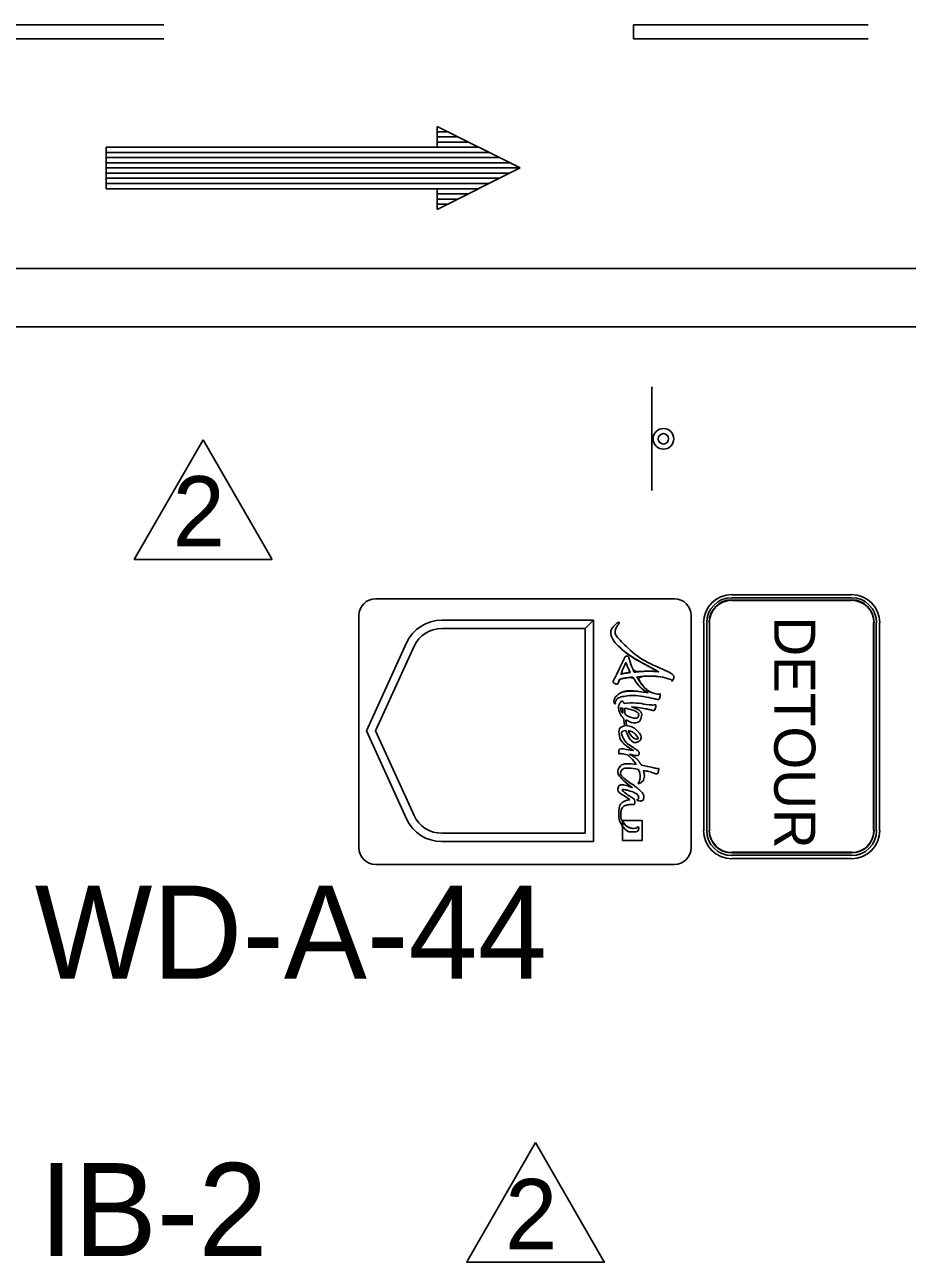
# Model space of a CAD drawing. Extents: x 1806 to 2022, y 110 to 389.
# Drawn here: x 1900.38 to 1918.56, y 195.64 to 221.16 of the extents above; entities that cross this region are included whole.
import ezdxf

# ---------------------------------------------------------------- set-up
doc = ezdxf.new("R2010")
doc.units = 0
for name, color, linetype in [('Level 10', 7, 'Continuous'), ('Level 2', 7, 'Continuous'), ('Level 44', 7, 'Continuous'), ('Level 50', 7, 'Continuous'), ('Level 53', 7, 'Continuous'), ('Level 60', 7, 'Continuous')]:
    doc.layers.add(name, color=color, linetype=linetype)

msp = doc.modelspace()

# ---------------------------------------------------------------- linework, layer by layer
at = {"layer": 'Level 10'}
for p, q in [((1895.86, 216.139), (1957.331, 216.139)), ((1895.86, 214.93), (1957.331, 214.93))]:
    msp.add_line(p, q, dxfattribs=at)
at = {"layer": 'Level 2'}
for p, q in [((1903.243, 221.163), (1898.405, 221.163)), ((1917.757, 221.163), (1912.919, 221.163)), ((1912.919, 221.163), (1912.919, 220.873)), ((1898.405, 220.873), (1903.243, 220.873)), ((1912.919, 220.873), (1917.757, 220.873)), ((1913.762, 209.325), (1907.607, 209.325)), ((1907.26, 208.978), (1907.26, 204.193)), ((1908.969, 208.883), (1912.096, 208.883)), ((1912.096, 208.883), (1911.925, 208.711)), ((1911.925, 208.711), (1912.096, 208.883)), ((1912.096, 208.883), (1912.096, 204.317)), ((1914.109, 208.978), (1914.109, 204.193)), ((1914.109, 208.978), (1914.109, 204.193)), ((1911.925, 208.711), (1908.969, 208.711)), ((1911.925, 204.488), (1911.925, 208.711)), ((1907.417, 206.6), (1908.242, 208.414)), ((1908.398, 208.344), (1907.605, 206.6)), ((1908.242, 204.785), (1907.417, 206.6)), ((1907.605, 206.6), (1908.398, 204.856)), ((1908.969, 204.488), (1911.925, 204.488)), ((1912.096, 204.317), (1908.969, 204.317)), ((1913.762, 203.846), (1907.607, 203.846))]:
    msp.add_line(p, q, dxfattribs=at)
for centre, radius, start, end in [((1907.607, 208.978), 0.347, 90, 180), ((1913.762, 208.978), 0.347, 360, 90), ((1908.969, 208.084), 0.799, 90, 155.5432), ((1908.969, 208.084), 0.628, 90, 155.5432), ((1908.969, 205.116), 0.799, 204.4568, 270), ((1908.969, 205.116), 0.628, 204.4568, 270), ((1907.607, 204.193), 0.347, 180, 270), ((1913.762, 204.193), 0.347, 270, 360)]:
    msp.add_arc(centre, radius, start, end, dxfattribs=at)
at = {"layer": 'Level 44'}
for p, q in [((1913.298, 213.694), (1913.298, 211.561)), ((1914.946, 209.297), (1917.411, 209.297)), ((1914.948, 209.406), (1917.413, 209.406)), ((1914.948, 209.341), (1917.413, 209.341)), ((1914.948, 209.287), (1917.413, 209.287)), ((1914.948, 209.287), (1917.413, 209.287)), ((1914.366, 204.54), (1914.366, 208.831)), ((1914.431, 204.54), (1914.431, 208.831)), ((1914.483, 204.55), (1914.483, 208.841)), ((1914.485, 204.54), (1914.485, 208.831)), ((1914.485, 204.54), (1914.485, 208.831)), ((1917.867, 208.841), (1917.867, 204.55)), ((1917.869, 208.831), (1917.869, 204.54)), ((1917.869, 208.831), (1917.869, 204.54)), ((1917.923, 208.831), (1917.923, 204.54)), ((1917.988, 208.831), (1917.988, 204.54)), ((1914.477, 206.475), (1914.477, 206.475)), ((1914.479, 206.465), (1914.479, 206.465)), ((1914.479, 206.465), (1914.479, 206.465)), ((1914.483, 204.544), (1914.485, 204.54)), ((1914.531, 204.568), (1914.533, 204.564)), ((1914.589, 204.597), (1914.591, 204.593)), ((1917.411, 204.098), (1914.946, 204.098)), ((1917.413, 204.088), (1914.948, 204.088)), ((1917.413, 204.088), (1914.948, 204.088)), ((1917.413, 204.034), (1914.948, 204.034)), ((1917.413, 203.969), (1914.948, 203.969))]:
    msp.add_line(p, q, dxfattribs=at)
for radius in [0.213, 0.107]:
    msp.add_circle((1913.537, 212.623), radius, dxfattribs=at)
for centre, radius, start, end in [((1914.944, 208.831), 0.581, 90, 180), ((1914.944, 208.831), 0.516, 90, 180), ((1914.942, 208.841), 0.462, 90, 180), ((1914.944, 208.831), 0.462, 90, 180), ((1914.944, 208.831), 0.462, 90, 180), ((1917.412, 208.841), 0.462, 0, 90), ((1917.414, 208.831), 0.581, 0, 90), ((1917.414, 208.831), 0.516, 0, 90), ((1917.414, 208.831), 0.462, 0, 90), ((1917.414, 208.831), 0.462, 0, 90), ((1914.944, 204.544), 0.581, 180, 270), ((1914.944, 204.544), 0.516, 180, 270), ((1914.942, 204.554), 0.462, 180, 270), ((1914.944, 204.544), 0.462, 180, 270), ((1914.944, 204.544), 0.462, 180, 270), ((1917.412, 204.554), 0.462, 270, 360), ((1917.414, 204.544), 0.462, 270, 360), ((1917.414, 204.544), 0.581, 270, 360), ((1917.414, 204.544), 0.516, 270, 360), ((1917.414, 204.544), 0.462, 270, 360)]:
    msp.add_arc(centre, radius, start, end, dxfattribs=at)
at = {"layer": 'Level 50'}
for p, q in [((1910.583, 218.209), (1908.876, 219.062)), ((1908.876, 219.062), (1908.876, 218.636)), ((1909.089, 218.956), (1908.876, 218.956)), ((1909.303, 218.849), (1908.876, 218.849)), ((1909.516, 218.742), (1908.876, 218.742)), ((1908.876, 218.636), (1902.05, 218.636)), ((1902.05, 218.636), (1902.05, 217.782)), ((1909.729, 218.636), (1902.05, 218.636)), ((1909.943, 218.529), (1902.05, 218.529)), ((1910.156, 218.422), (1902.05, 218.422)), ((1910.369, 218.316), (1902.05, 218.316)), ((1910.583, 218.209), (1902.05, 218.209)), ((1910.583, 218.209), (1908.876, 217.356)), ((1910.369, 218.102), (1902.05, 218.102)), ((1910.156, 217.996), (1902.05, 217.996)), ((1909.943, 217.889), (1902.05, 217.889)), ((1908.876, 217.782), (1902.05, 217.782)), ((1909.729, 217.782), (1902.05, 217.782)), ((1908.876, 217.782), (1908.876, 217.356)), ((1909.516, 217.676), (1908.876, 217.676)), ((1909.303, 217.569), (1908.876, 217.569)), ((1909.089, 217.462), (1908.876, 217.462))]:
    msp.add_line(p, q, dxfattribs=at)
at = {"layer": 'Level 53'}
msp.add_line((1912.692, 204.637), (1912.692, 204.737), dxfattribs=at)
msp.add_lwpolyline([(1912.692, 204.637), (1912.692, 204.342), (1913.099, 204.342), (1913.099, 204.749), (1912.692, 204.749), (1912.692, 204.737)], dxfattribs=at)
for points, degree in [([(1912.544, 207.191), (1912.551, 207.235), (1912.61, 207.292), (1912.708, 207.31), (1912.885, 207.341), (1913.059, 207.322), (1913.318, 207.27), (1913.368, 207.261), (1913.453, 207.227), (1913.469, 207.334), (1913.474, 207.368), (1913.458, 207.35), (1913.413, 207.36), (1913.219, 207.4), (1913.08, 207.559), (1912.987, 207.717), (1913.208, 207.734), (1913.454, 207.727), (1913.604, 207.685), (1913.732, 207.65), (1913.708, 207.608), (1913.735, 207.66), (1913.763, 207.715), (1913.726, 207.774), (1913.631, 207.821), (1913.537, 207.868), (1913.022, 208.087), (1912.675, 208.436), (1912.497, 208.615), (1912.589, 208.776), (1912.616, 208.809), (1912.639, 208.835), (1912.604, 208.845), (1912.569, 208.812), (1912.413, 208.668), (1912.503, 208.456), (1912.579, 208.38), (1912.792, 208.167), (1913.249, 207.92), (1913.443, 207.82), (1913.333, 207.83), (1913.15, 207.833), (1912.936, 207.812), (1912.883, 207.921), (1912.852, 208.017), (1912.84, 208.063), (1912.827, 208.113), (1912.807, 208.143), (1912.784, 208.144), (1912.759, 208.145), (1912.738, 208.112), (1912.715, 208.064), (1912.674, 207.978), (1912.556, 207.728), (1912.52, 207.666), (1912.489, 207.613), (1912.513, 207.587), (1912.546, 207.572), (1912.59, 207.551), (1912.614, 207.607), (1912.631, 207.662), (1912.703, 207.683), (1912.801, 207.699), (1912.909, 207.71), (1912.987, 207.583), (1913.092, 207.458), (1913.222, 207.385), (1913.113, 207.404), (1912.742, 207.45), (1912.586, 207.333), (1912.551, 207.307), (1912.513, 207.25), (1912.519, 207.195), (1912.521, 207.169), (1912.539, 207.155), (1912.544, 207.158), (1912.549, 207.161), (1912.542, 207.176), (1912.544, 207.191)], 3), ([(1912.987, 207.717), (1913.208, 207.734), (1913.454, 207.727), (1913.604, 207.685), (1913.732, 207.65), (1913.708, 207.608), (1913.735, 207.66), (1913.763, 207.715), (1913.726, 207.774), (1913.631, 207.821), (1913.537, 207.868), (1913.022, 208.087), (1912.675, 208.436), (1912.497, 208.615), (1912.589, 208.776), (1912.616, 208.809), (1912.639, 208.835), (1912.604, 208.845), (1912.569, 208.812), (1912.413, 208.668), (1912.503, 208.456), (1912.579, 208.38), (1912.792, 208.167), (1913.249, 207.92), (1913.443, 207.82)], 3), ([(1912.936, 207.812), (1912.883, 207.921), (1912.852, 208.017), (1912.84, 208.063), (1912.827, 208.113), (1912.807, 208.143), (1912.784, 208.144), (1912.759, 208.145), (1912.738, 208.112), (1912.715, 208.064), (1912.674, 207.978), (1912.556, 207.728), (1912.52, 207.666), (1912.489, 207.613), (1912.513, 207.587), (1912.546, 207.572), (1912.59, 207.551), (1912.614, 207.607), (1912.631, 207.662)], 3), ([(1912.661, 207.77), (1912.681, 207.826), (1912.713, 207.905), (1912.765, 208.008)], 2), ([(1912.765, 208.008), (1912.786, 207.951), (1912.816, 207.88), (1912.856, 207.804), (1912.769, 207.794), (1912.707, 207.783), (1912.661, 207.77), (1912.681, 207.826), (1912.713, 207.905), (1912.765, 208.008)], 3), ([(1912.765, 208.008), (1912.786, 207.951), (1912.816, 207.88), (1912.856, 207.804)], 2), ([(1912.856, 207.804), (1912.769, 207.794), (1912.707, 207.783), (1912.661, 207.77)], 2), ([(1913.443, 207.82), (1913.333, 207.83), (1913.15, 207.833), (1912.936, 207.812)], 2), ([(1912.544, 207.191), (1912.551, 207.235), (1912.61, 207.292), (1912.708, 207.31), (1912.885, 207.341), (1913.059, 207.322), (1913.318, 207.27), (1913.368, 207.261), (1913.453, 207.227), (1913.469, 207.334), (1913.474, 207.368), (1913.458, 207.35), (1913.413, 207.36), (1913.219, 207.4), (1913.08, 207.559), (1912.987, 207.717)], 3), ([(1912.631, 207.662), (1912.703, 207.683), (1912.801, 207.699), (1912.909, 207.71)], 2), ([(1912.909, 207.71), (1912.987, 207.583), (1913.092, 207.458), (1913.222, 207.385)], 2), ([(1913.222, 207.385), (1913.113, 207.404), (1912.742, 207.45), (1912.586, 207.333), (1912.551, 207.307), (1912.513, 207.25), (1912.519, 207.195), (1912.521, 207.169), (1912.539, 207.155), (1912.544, 207.158), (1912.549, 207.161), (1912.542, 207.176), (1912.544, 207.191)], 3), ([(1912.725, 207.162), (1912.71, 207.208), (1912.675, 207.227), (1912.639, 207.168), (1912.614, 207.127), (1912.606, 207.038), (1912.65, 206.947), (1912.666, 206.915), (1912.689, 206.887), (1912.715, 206.863)], 3), ([(1912.657, 207.042), (1912.655, 207.057), (1912.655, 207.07), (1912.657, 207.079)], 2), ([(1912.657, 207.079), (1912.662, 207.073), (1912.669, 207.07), (1912.678, 207.07), (1912.684, 207.07), (1912.69, 207.07), (1912.696, 207.069)], 3), ([(1912.703, 206.968), (1912.679, 206.99), (1912.662, 207.015), (1912.657, 207.042)], 2), ([(1912.696, 207.069), (1912.697, 207.046), (1912.699, 207.01), (1912.703, 206.968)], 2), ([(1912.88, 207.093), (1912.984, 207.085), (1913.111, 207.068), (1913.228, 207.045), (1913.277, 207.035), (1913.362, 207.001), (1913.379, 207.108), (1913.384, 207.142), (1913.368, 207.136), (1913.322, 207.134), (1913.261, 207.13), (1912.888, 207.198), (1912.725, 207.162)], 3), ([(1912.747, 206.935), (1912.743, 206.976), (1912.74, 207.02), (1912.736, 207.066)], 2), ([(1912.736, 207.066), (1912.867, 207.048), (1913.048, 206.98), (1913.019, 206.896), (1913.002, 206.847), (1912.849, 206.872), (1912.747, 206.935)], 3), ([(1912.76, 206.83), (1912.883, 206.755), (1913.049, 206.761), (1913.077, 206.872), (1913.109, 207.001), (1912.984, 207.066), (1912.88, 207.093)], 3), ([(1912.715, 206.863), (1912.722, 206.81), (1912.731, 206.753), (1912.741, 206.701)], 2), ([(1912.781, 206.703), (1912.773, 206.74), (1912.766, 206.783), (1912.76, 206.83)], 2), ([(1912.741, 206.701), (1912.669, 206.693), (1912.614, 206.646), (1912.624, 206.537), (1912.639, 206.382), (1912.829, 206.245), (1912.92, 206.193)], 3), ([(1912.839, 206.118), (1912.89, 206.108), (1912.946, 206.092), (1912.984, 206.091), (1913.023, 206.09), (1913.032, 206.117), (1913.035, 206.128), (1913.042, 206.151), (1913.03, 206.178), (1912.991, 206.206), (1912.901, 206.271), (1912.757, 206.352), (1912.696, 206.476), (1912.653, 206.565), (1912.697, 206.604), (1912.764, 206.607)], 3), ([(1912.764, 206.607), (1912.769, 206.589), (1912.775, 206.573), (1912.781, 206.56), (1912.852, 206.399), (1912.96, 206.343), (1913.025, 206.384), (1913.088, 206.423), (1913.069, 206.534), (1912.976, 206.622), (1912.931, 206.665), (1912.853, 206.699), (1912.781, 206.703)], 3), ([(1912.968, 206.52), (1913.018, 206.466), (1913.015, 206.439), (1913.001, 206.432), (1912.972, 206.417), (1912.869, 206.481), (1912.813, 206.602)], 3), ([(1912.813, 206.602), (1912.868, 206.592), (1912.929, 206.563), (1912.968, 206.52)], 2), ([(1912.92, 206.193), (1912.822, 206.203), (1912.608, 206.267), (1912.619, 206.158), (1912.623, 206.115), (1912.63, 206.134), (1912.667, 206.131), (1912.796, 206.122), (1912.905, 206.014), (1912.972, 205.908)], 3), ([(1913.082, 205.892), (1913.032, 205.978), (1912.949, 206.059), (1912.839, 206.118)], 2), ([(1912.972, 205.908), (1912.814, 205.926), (1912.673, 205.92), (1912.628, 205.848), (1912.546, 205.716), (1912.763, 205.53), (1912.896, 205.427)], 3), ([(1912.656, 204.863), (1912.656, 205.03), (1912.786, 205.074), (1912.85, 205.082), (1912.893, 205.087), (1912.955, 205.078), (1912.946, 205.152), (1912.941, 205.203), (1912.84, 205.25), (1912.755, 205.316), (1912.682, 205.372), (1912.689, 205.397), (1912.752, 205.384), (1912.83, 205.368), (1913.014, 205.302), (1913.027, 205.228), (1913.033, 205.193), (1912.972, 205.181), (1913.011, 205.165), (1913.049, 205.149), (1913.131, 205.164), (1913.131, 205.241), (1913.131, 205.295), (1913.073, 205.36), (1913.008, 205.413), (1912.951, 205.46), (1912.605, 205.694), (1912.68, 205.793), (1912.715, 205.839), (1912.857, 205.835), (1913.024, 205.806)], 3), ([(1913.024, 205.806), (1913.069, 205.689), (1913.054, 205.592), (1913.028, 205.537), (1913.015, 205.51), (1913.017, 205.506), (1913.047, 205.518), (1913.091, 205.535), (1913.159, 205.629), (1913.128, 205.776), (1913.127, 205.779), (1913.126, 205.783), (1913.125, 205.786)], 3), ([(1913.125, 205.786), (1913.18, 205.775), (1913.235, 205.761), (1913.288, 205.746), (1913.338, 205.732), (1913.423, 205.692), (1913.439, 205.797), (1913.444, 205.83), (1913.428, 205.816), (1913.383, 205.827), (1913.299, 205.848), (1913.191, 205.873), (1913.082, 205.892)], 3), ([(1912.896, 205.427), (1912.778, 205.479), (1912.627, 205.509), (1912.604, 205.43), (1912.577, 205.338), (1912.73, 205.265), (1912.847, 205.18)], 3), ([(1912.847, 205.18), (1912.763, 205.17), (1912.618, 205.114), (1912.618, 204.889), (1912.618, 204.787), (1912.647, 204.701), (1912.692, 204.637)], 3), ([(1912.692, 204.737), (1912.669, 204.775), (1912.656, 204.818), (1912.656, 204.863)], 2), ([(1913.099, 204.749), (1913.099, 204.749), (1912.692, 204.749), (1912.692, 204.749), (1912.692, 204.749), (1912.692, 204.737), (1912.692, 204.737), (1912.745, 204.649), (1912.846, 204.59), (1912.929, 204.59), (1913.001, 204.59), (1912.998, 204.628), (1913.008, 204.624), (1913.037, 204.611), (1913.02, 204.521), (1912.918, 204.516), (1912.832, 204.512), (1912.749, 204.557), (1912.692, 204.637), (1912.692, 204.637), (1912.692, 204.342), (1912.692, 204.342), (1912.692, 204.342), (1913.099, 204.342), (1913.099, 204.342), (1913.099, 204.342), (1913.099, 204.749), (1913.099, 204.749)], 3), ([(1912.692, 204.737), (1912.745, 204.649), (1912.846, 204.59), (1912.929, 204.59), (1913.001, 204.59), (1912.998, 204.628), (1913.008, 204.624), (1913.037, 204.611), (1913.02, 204.521), (1912.918, 204.516), (1912.832, 204.512), (1912.749, 204.557), (1912.692, 204.637)], 3)]:
    msp.add_open_spline(points, degree=degree, dxfattribs=at)
at = {"layer": 'Level 60'}
for points in [[(1904.05, 212.606), (1902.657, 210.181)], [(1905.444, 210.181), (1904.05, 212.606)], [(1902.657, 210.181), (1902.631, 210.136), (1905.47, 210.136), (1905.444, 210.181)], [(1910.901, 198.112), (1909.508, 195.687)], [(1912.295, 195.687), (1910.901, 198.112)], [(1909.508, 195.687), (1909.482, 195.642), (1912.321, 195.642), (1912.295, 195.687)]]:
    msp.add_lwpolyline(points, dxfattribs=at)

# ---------------------------------------------------------------- texts
at = {"layer": 'Level 44'}
msp.add_text('DETOUR', height=0.848, rotation=270, dxfattribs=at).set_placement((1915.819, 208.96))
at = {"layer": 'Level 50'}
for s, height, p in [('WD-A-44', 1.92, (1900.582, 201.49)), ('IB-2', 1.9199, (1900.673, 195.769))]:
    msp.add_text(s, height=height, rotation=360, dxfattribs=at).set_placement(p)
at = {"layer": 'Level 60'}
for p in [(1903.423, 210.405), (1910.274, 195.911)]:
    msp.add_text('2', height=1.448, rotation=360, dxfattribs=at).set_placement(p)

doc.saveas('drawing.dxf')
